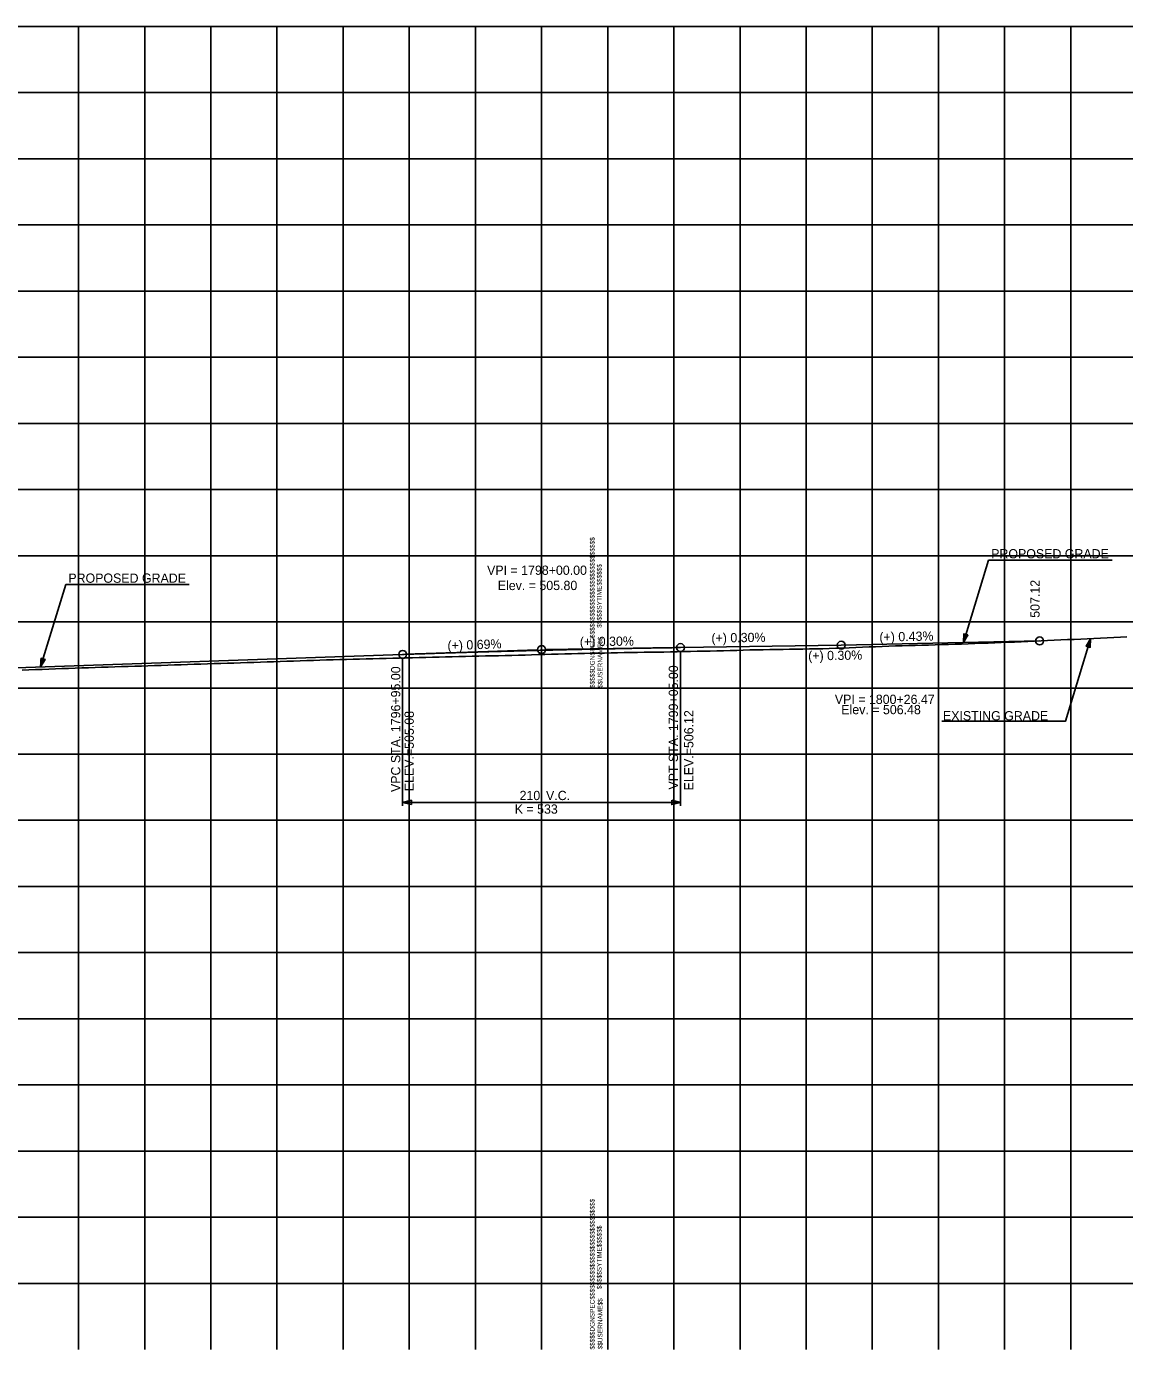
# Model space of a CAD drawing. Extents: x -90830 to 2015517, y -20856 to 836331.
# Drawn here: x 68334 to 69164, y -9797 to -8797 of the extents above; entities that cross this region are included whole.
import ezdxf

# ---------------------------------------------------------------- set-up
doc = ezdxf.new("R2010")
doc.units = 0
for name, color, linetype in [('Level 1', 7, 'Continuous'), ('RD_DDB_GradeTX', 7, 'Continuous'), ('RD_DDB_Profile_EX', 7, 'Continuous'), ('RD_DDB_Profile_Lbl', 7, 'Continuous'), ('RD_DDB_Profile_PR', 7, 'Continuous'), ('RD_DDB_StripGrade', 7, 'Continuous'), ('RD_DDB_VCLbl', 7, 'Continuous'), ('RD_PD_Final_TX', 7, 'Continuous')]:
    doc.layers.add(name, color=color, linetype=linetype)

msp = doc.modelspace()

# ---------------------------------------------------------------- linework, layer by layer
at = {"layer": 'Level 1'}
for p, q in [((67173.46, -8797.12), (68773.46, -8797.12)), ((68373.46, -8797.12), (68373.46, -9297.12)), ((68423.46, -8797.12), (68423.46, -9297.12)), ((68473.46, -8797.12), (68473.46, -9297.12)), ((68523.46, -8797.12), (68523.46, -9297.12)), ((68573.46, -8797.12), (68573.46, -9297.12)), ((68623.46, -8797.12), (68623.46, -9297.12)), ((68673.46, -8797.12), (68673.46, -9297.12)), ((68723.46, -8797.12), (68723.46, -9297.12)), ((68773.46, -8797.12), (68773.46, -9297.12)), ((68773.46, -8797.12), (68773.46, -9297.12)), ((68773.46, -8797.12), (70373.46, -8797.12)), ((68773.46, -8797.12), (68773.46, -9297.12)), ((68823.46, -8797.12), (68823.46, -9297.12)), ((68873.46, -8797.12), (68873.46, -9297.12)), ((68923.46, -8797.12), (68923.46, -9297.12)), ((68973.46, -8797.12), (68973.46, -9297.12)), ((69023.46, -8797.12), (69023.46, -9297.12)), ((69073.46, -8797.12), (69073.46, -9297.12)), ((69123.46, -8797.12), (69123.46, -9297.12)), ((67173.46, -8847.12), (68773.46, -8847.12)), ((68773.46, -8847.12), (70373.46, -8847.12)), ((67173.46, -8897.12), (68773.46, -8897.12)), ((68773.46, -8897.12), (70373.46, -8897.12)), ((67173.46, -8947.12), (68773.46, -8947.12)), ((68773.46, -8947.12), (70373.46, -8947.12)), ((67173.46, -8997.12), (68773.46, -8997.12)), ((68773.46, -8997.12), (70373.46, -8997.12)), ((67173.46, -9047.12), (68773.46, -9047.12)), ((68773.46, -9047.12), (70373.46, -9047.12)), ((67173.46, -9097.12), (68773.46, -9097.12)), ((68773.46, -9097.12), (70373.46, -9097.12)), ((67173.46, -9147.12), (68773.46, -9147.12)), ((68773.46, -9147.12), (70373.46, -9147.12)), ((67173.46, -9197.12), (68773.46, -9197.12)), ((68773.46, -9197.12), (70373.46, -9197.12)), ((67173.46, -9247.12), (68773.46, -9247.12)), ((68773.46, -9247.12), (70373.46, -9247.12)), ((67173.46, -9297.12), (68773.46, -9297.12)), ((67173.46, -9297.12), (68773.46, -9297.12)), ((68373.46, -9297.12), (68373.46, -9797.12)), ((68423.46, -9297.12), (68423.46, -9797.12)), ((68473.46, -9297.12), (68473.46, -9797.12)), ((68523.46, -9297.12), (68523.46, -9797.12)), ((68573.46, -9297.12), (68573.46, -9797.12)), ((68623.46, -9297.12), (68623.46, -9797.12)), ((68673.46, -9297.12), (68673.46, -9797.12)), ((68723.46, -9297.12), (68723.46, -9797.12)), ((68773.46, -9297.12), (68773.46, -9797.12)), ((68773.46, -9297.12), (68773.46, -9797.12)), ((68773.46, -9297.12), (70373.46, -9297.12)), ((68773.46, -9297.12), (70373.46, -9297.12)), ((68773.46, -9297.12), (68773.46, -9797.12)), ((68823.46, -9297.12), (68823.46, -9797.12)), ((68873.46, -9297.12), (68873.46, -9797.12)), ((68923.46, -9297.12), (68923.46, -9797.12)), ((68973.46, -9297.12), (68973.46, -9797.12)), ((69023.46, -9297.12), (69023.46, -9797.12)), ((69073.46, -9297.12), (69073.46, -9797.12)), ((69123.46, -9297.12), (69123.46, -9797.12)), ((67173.46, -9347.12), (68773.46, -9347.12)), ((68773.46, -9347.12), (70373.46, -9347.12)), ((67173.46, -9397.12), (68773.46, -9397.12)), ((68773.46, -9397.12), (70373.46, -9397.12)), ((67173.46, -9447.12), (68773.46, -9447.12)), ((68773.46, -9447.12), (70373.46, -9447.12)), ((67173.46, -9497.12), (68773.46, -9497.12)), ((68773.46, -9497.12), (70373.46, -9497.12)), ((67173.46, -9547.12), (68773.46, -9547.12)), ((68773.46, -9547.12), (70373.46, -9547.12)), ((67173.46, -9597.12), (68773.46, -9597.12)), ((68773.46, -9597.12), (70373.46, -9597.12)), ((67173.46, -9647.12), (68773.46, -9647.12)), ((68773.46, -9647.12), (70373.46, -9647.12)), ((67173.46, -9697.12), (68773.46, -9697.12)), ((68773.46, -9697.12), (70373.46, -9697.12)), ((67173.46, -9747.12), (68773.46, -9747.12)), ((68773.46, -9747.12), (70373.46, -9747.12))]:
    msp.add_line(p, q, dxfattribs=at)
at = {"layer": 'RD_DDB_GradeTX'}
for p, q in [((68652.5, -9270.56), (68720.46, -9268.21)), ((68794.45, -9267.05), (68726.46, -9268.06))]:
    msp.add_line(p, q, dxfattribs=at)
for centre in [(69099.93, -9261.54), (68723.46, -9268.1), (68949.93, -9264.73)]:
    msp.add_circle(centre, 3, dxfattribs=at)
at = {"layer": 'RD_DDB_Profile_EX'}
for points in [[(68920.95, -9267.68), (68925.95, -9267.6), (68930.95, -9267.51), (68935.95, -9267.43), (68940.95, -9267.28), (68945.95, -9267.09), (68950.95, -9266.9), (68955.95, -9266.72), (68960.95, -9266.52), (68965.95, -9266.3), (68970.95, -9266.09), (68975.95, -9265.88), (68980.95, -9265.69), (68985.95, -9265.52), (68990.95, -9265.36), (68995.95, -9265.19), (69000.95, -9265.04), (69005.95, -9264.9), (69010.95, -9264.77), (69015.95, -9264.64), (69020.95, -9264.5), (69025.95, -9264.35), (69030.95, -9264.2), (69035.95, -9264.05), (69040.95, -9263.88), (69045.95, -9263.69), (69050.95, -9263.49), (69055.95, -9263.3), (69060.95, -9263.11), (69065.95, -9262.92), (69070.95, -9262.74), (69075.95, -9262.55), (69080.95, -9262.36), (69085.95, -9262.14), (69090.95, -9261.92), (69095.95, -9261.71), (69100.95, -9261.5), (69105.95, -9261.26), (69110.95, -9261.03), (69115.95, -9260.8), (69120.95, -9260.58), (69125.95, -9260.36), (69130.95, -9260.15), (69135.95, -9259.94), (69140.95, -9259.73), (69145.95, -9259.5), (69150.95, -9259.27), (69155.95, -9259.04), (69160.95, -9258.81), (69165.95, -9258.57)], [(68420.95, -9280.51), (68425.95, -9280.35), (68430.95, -9280.18), (68435.95, -9280.02), (68440.95, -9279.85), (68445.95, -9279.69), (68450.95, -9279.54), (68455.95, -9279.39), (68460.95, -9279.22), (68465.95, -9279.04), (68470.95, -9278.86), (68475.95, -9278.69), (68480.95, -9278.53), (68485.95, -9278.38), (68490.95, -9278.23), (68495.95, -9278.08), (68500.95, -9277.91), (68505.95, -9277.74), (68510.95, -9277.57), (68515.95, -9277.39), (68520.95, -9277.23), (68525.95, -9277.07), (68530.95, -9276.92), (68535.95, -9276.76), (68540.95, -9276.59), (68545.95, -9276.42), (68550.95, -9276.25), (68555.95, -9276.08), (68560.95, -9275.94), (68565.95, -9275.81), (68570.95, -9275.68), (68575.95, -9275.54), (68580.95, -9275.41), (68585.95, -9275.29), (68590.95, -9275.16), (68595.95, -9275.05), (68600.95, -9274.92), (68605.95, -9274.8), (68610.95, -9274.68), (68615.95, -9274.56), (68620.95, -9274.44), (68625.95, -9274.32), (68630.95, -9274.19), (68635.95, -9274.06), (68640.95, -9273.92), (68645.95, -9273.79), (68650.95, -9273.65), (68655.95, -9273.51), (68660.95, -9273.38), (68665.95, -9273.26), (68670.95, -9273.14), (68675.95, -9273.01), (68680.95, -9272.9), (68685.95, -9272.8), (68690.95, -9272.7), (68695.95, -9272.6), (68700.95, -9272.47), (68705.95, -9272.33), (68710.95, -9272.19), (68715.95, -9272.05), (68720.95, -9271.91), (68725.95, -9271.78), (68730.95, -9271.64), (68735.95, -9271.51), (68740.95, -9271.38), (68745.95, -9271.26), (68750.95, -9271.14), (68755.95, -9271.02), (68760.95, -9270.91), (68765.95, -9270.79), (68770.95, -9270.67), (68775.95, -9270.56), (68780.95, -9270.46), (68785.95, -9270.38), (68790.95, -9270.29), (68795.95, -9270.21), (68800.95, -9270.13), (68805.95, -9270.06), (68810.95, -9269.99), (68815.95, -9269.92), (68820.95, -9269.82), (68825.95, -9269.72), (68830.95, -9269.61), (68835.95, -9269.5), (68840.95, -9269.4), (68845.95, -9269.29), (68850.95, -9269.19), (68855.95, -9269.08), (68860.95, -9268.94), (68865.95, -9268.8), (68870.95, -9268.65), (68875.95, -9268.5), (68880.95, -9268.39), (68885.95, -9268.29), (68890.95, -9268.2), (68895.95, -9268.11), (68900.95, -9268.02), (68905.95, -9267.93), (68910.95, -9267.85), (68915.95, -9267.77), (68920.95, -9267.68)], [(68330.95, -9283.56), (68335.95, -9283.4), (68340.95, -9283.22), (68345.95, -9283.04), (68350.95, -9282.86), (68355.95, -9282.68), (68360.95, -9282.5), (68365.95, -9282.32), (68370.95, -9282.14), (68375.95, -9281.97), (68380.95, -9281.79), (68385.95, -9281.62), (68390.95, -9281.44), (68395.95, -9281.27), (68400.95, -9281.11), (68405.95, -9280.96), (68410.95, -9280.81), (68415.95, -9280.67), (68420.95, -9280.51)]]:
    msp.add_lwpolyline(points, dxfattribs=at)
at = {"layer": 'RD_DDB_Profile_PR'}
for p, q in [((68828.46, -9266.54), (68949.93, -9264.73)), ((68949.93, -9264.73), (69099.93, -9261.54)), ((68028.46, -9292.15), (68618.46, -9271.74))]:
    msp.add_line(p, q, dxfattribs=at)
msp.add_spline([(68618.46, -9271.74), (68622.66, -9271.59), (68626.86, -9271.45), (68631.06, -9271.31), (68635.26, -9271.17), (68639.46, -9271.03), (68643.66, -9270.9), (68647.86, -9270.76), (68652.06, -9270.63), (68656.26, -9270.5), (68660.46, -9270.37), (68664.66, -9270.24), (68668.86, -9270.11), (68673.06, -9269.99), (68677.26, -9269.87), (68681.46, -9269.74), (68685.66, -9269.62), (68689.86, -9269.51), (68694.06, -9269.39), (68698.26, -9269.28), (68702.46, -9269.16), (68706.66, -9269.05), (68710.86, -9268.94), (68715.06, -9268.83), (68719.26, -9268.73), (68723.46, -9268.62), (68727.66, -9268.52), (68731.86, -9268.42), (68736.06, -9268.32), (68740.26, -9268.22), (68744.46, -9268.12), (68748.66, -9268.03), (68752.86, -9267.94), (68757.06, -9267.84), (68761.26, -9267.75), (68765.46, -9267.67), (68769.66, -9267.58), (68773.86, -9267.49), (68778.06, -9267.41), (68782.26, -9267.33), (68786.46, -9267.25), (68790.66, -9267.17), (68794.86, -9267.1), (68799.06, -9267.02), (68803.26, -9266.95), (68807.46, -9266.88), (68811.66, -9266.81), (68815.86, -9266.74), (68820.06, -9266.67), (68824.26, -9266.61), (68828.46, -9266.54)], degree=3, dxfattribs=at)
at = {"layer": 'RD_DDB_VCLbl'}
for p, q in [((68828.46, -9386.12), (68828.46, -9269.54)), ((68618.46, -9386.12), (68618.46, -9274.74)), ((68618.46, -9383.62), (68828.46, -9383.62))]:
    msp.add_line(p, q, dxfattribs=at)
for centre in [(68618.46, -9271.74), (68828.46, -9266.54)]:
    msp.add_circle(centre, 3, dxfattribs=at)
at = {"layer": 'RD_PD_Final_TX'}
for p, q in [((69042.28, -9262.77), (69061.34, -9200.4)), ((69061.34, -9200.4), (69154.72, -9200.4)), ((68344.76, -9281.21), (68363.81, -9218.84)), ((68363.81, -9218.84), (68457.2, -9218.84)), ((69042.28, -9262.77), (69042.63, -9256.1)), ((69044.17, -9256.57), (69042.28, -9262.77)), ((69042.28, -9262.77), (69045.72, -9257.04)), ((69042.63, -9256.1), (69045.72, -9257.04)), ((69138.45, -9259.84), (69135.01, -9265.56)), ((69136.56, -9266.03), (69138.45, -9259.84)), ((69138.45, -9259.84), (69138.11, -9266.51)), ((69138.11, -9266.51), (69135.01, -9265.56)), ((68344.76, -9281.21), (68345.1, -9274.54)), ((68346.65, -9275.01), (68344.76, -9281.21)), ((68344.76, -9281.21), (68348.2, -9275.48)), ((68345.1, -9274.54), (68348.2, -9275.48))]:
    msp.add_line(p, q, dxfattribs=at)
for points in [[(69026.01, -9322.21), (69119.4, -9322.21), (69138.45, -9259.84)], [(69044.11, -9256.63), (69042.34, -9262.4), (69044.08, -9256.58), (69042.37, -9262.12), (69044.01, -9256.59), (69042.38, -9261.92), (69043.93, -9256.58), (69042.38, -9261.69), (69043.87, -9256.55), (69042.41, -9261.33), (69043.78, -9256.51), (69042.44, -9260.95), (69043.7, -9256.51), (69042.46, -9260.66), (69043.64, -9256.48), (69042.47, -9260.33), (69043.56, -9256.49), (69042.49, -9260.04), (69043.51, -9256.42), (69042.5, -9259.79), (69043.41, -9256.42), (69042.51, -9259.43), (69043.34, -9256.39), (69042.56, -9258.99), (69043.27, -9256.35), (69042.54, -9258.69), (69043.19, -9256.33), (69042.56, -9258.24), (69043.11, -9256.33), (69042.61, -9257.87), (69043.03, -9256.26), (69042.62, -9257.55), (69042.96, -9256.27), (69042.62, -9257.26), (69042.89, -9256.21), (69042.65, -9256.9), (69042.81, -9256.24), (69042.67, -9256.5), (69042.73, -9256.24)], [(69042.45, -9262.38), (69044.2, -9256.66), (69042.55, -9262.19), (69044.27, -9256.68), (69042.65, -9262), (69044.33, -9256.67), (69042.77, -9261.84), (69044.38, -9256.7), (69042.9, -9261.65), (69044.45, -9256.71), (69043.01, -9261.46), (69044.5, -9256.72), (69043.15, -9261.23), (69044.57, -9256.73), (69043.3, -9260.96), (69044.65, -9256.77), (69043.43, -9260.72), (69044.71, -9256.76), (69043.58, -9260.47), (69044.77, -9256.79), (69043.73, -9260.23), (69044.84, -9256.81), (69043.89, -9259.97), (69044.88, -9256.87), (69044.09, -9259.63), (69044.95, -9256.86), (69044.24, -9259.41), (69045.01, -9256.85), (69044.43, -9259.11), (69045.06, -9256.9), (69044.58, -9258.81), (69045.14, -9256.93), (69044.72, -9258.57), (69045.2, -9257), (69044.88, -9258.36), (69045.25, -9257.01), (69045.06, -9258), (69045.36, -9256.99), (69045.18, -9257.8), (69045.46, -9257.02), (69045.3, -9257.67), (69045.54, -9257.11), (69045.63, -9257.07), (69045.52, -9257.11)], [(69138.28, -9260.22), (69136.54, -9265.94), (69138.18, -9260.42), (69136.46, -9265.92), (69138.08, -9260.6), (69136.4, -9265.93), (69137.96, -9260.76), (69136.35, -9265.9), (69137.83, -9260.96), (69136.28, -9265.89), (69137.72, -9261.15), (69136.23, -9265.88), (69137.58, -9261.37), (69136.16, -9265.87), (69137.43, -9261.65), (69136.08, -9265.83), (69137.3, -9261.89), (69136.02, -9265.84), (69137.15, -9262.14), (69135.96, -9265.81), (69137, -9262.37), (69135.9, -9265.79), (69136.85, -9262.63), (69135.86, -9265.73), (69136.64, -9262.98), (69135.78, -9265.74), (69136.49, -9263.2), (69135.72, -9265.75), (69136.3, -9263.49), (69135.67, -9265.71), (69136.15, -9263.79), (69135.6, -9265.67), (69136.01, -9264.03), (69135.53, -9265.61), (69135.85, -9264.25), (69135.48, -9265.59), (69135.67, -9264.6), (69135.37, -9265.62), (69135.55, -9264.8), (69135.27, -9265.58), (69135.43, -9264.93), (69135.19, -9265.49), (69135.1, -9265.53), (69135.21, -9265.5)], [(69136.62, -9265.97), (69138.39, -9260.2), (69136.65, -9266.02), (69138.36, -9260.49), (69136.72, -9266.01), (69138.35, -9260.68), (69136.8, -9266.02), (69138.35, -9260.92), (69136.86, -9266.06), (69138.33, -9261.27), (69136.95, -9266.1), (69138.29, -9261.66), (69137.04, -9266.1), (69138.27, -9261.95), (69137.1, -9266.13), (69138.26, -9262.28), (69137.17, -9266.11), (69138.24, -9262.57), (69137.22, -9266.18), (69138.23, -9262.82), (69137.32, -9266.18), (69138.22, -9263.18), (69137.39, -9266.22), (69138.17, -9263.61), (69137.46, -9266.25), (69138.19, -9263.91), (69137.54, -9266.28), (69138.17, -9264.37), (69137.62, -9266.28), (69138.12, -9264.73), (69137.7, -9266.34), (69138.11, -9265.05), (69137.77, -9266.34), (69138.11, -9265.34), (69137.84, -9266.4), (69138.08, -9265.7), (69137.92, -9266.37), (69138.06, -9266.1), (69138, -9266.36)], [(68346.58, -9275.07), (68344.82, -9280.84), (68346.55, -9275.02), (68344.85, -9280.56), (68346.48, -9275.03), (68344.85, -9280.36), (68346.4, -9275.02), (68344.85, -9280.12), (68346.34, -9274.99), (68344.88, -9279.77), (68346.25, -9274.94), (68344.91, -9279.39), (68346.17, -9274.95), (68344.93, -9279.1), (68346.11, -9274.91), (68344.95, -9278.77), (68346.03, -9274.93), (68344.97, -9278.48), (68345.99, -9274.86), (68344.97, -9278.23), (68345.89, -9274.86), (68344.98, -9277.87), (68345.81, -9274.82), (68345.03, -9277.43), (68345.74, -9274.79), (68345.01, -9277.13), (68345.66, -9274.76), (68345.04, -9276.68), (68345.58, -9274.77), (68345.08, -9276.31), (68345.5, -9274.7), (68345.09, -9275.99), (68345.43, -9274.71), (68345.1, -9275.7), (68345.36, -9274.65), (68345.12, -9275.34), (68345.28, -9274.68), (68345.15, -9274.94), (68345.2, -9274.68)], [(68344.92, -9280.82), (68346.67, -9275.1), (68345.02, -9280.62), (68346.75, -9275.12), (68345.12, -9280.44), (68346.81, -9275.11), (68345.24, -9280.28), (68346.85, -9275.14), (68345.37, -9280.09), (68346.92, -9275.15), (68345.48, -9279.9), (68346.97, -9275.16), (68345.62, -9279.67), (68347.04, -9275.17), (68345.78, -9279.4), (68347.13, -9275.21), (68345.91, -9279.16), (68347.19, -9275.2), (68346.05, -9278.91), (68347.25, -9275.23), (68346.21, -9278.67), (68347.31, -9275.25), (68346.36, -9278.41), (68347.35, -9275.31), (68346.56, -9278.07), (68347.42, -9275.3), (68346.71, -9277.85), (68347.48, -9275.29), (68346.9, -9277.55), (68347.54, -9275.34), (68347.05, -9277.25), (68347.61, -9275.37), (68347.19, -9277.01), (68347.67, -9275.43), (68347.36, -9276.8), (68347.73, -9275.45), (68347.53, -9276.44), (68347.83, -9275.43), (68347.65, -9276.24), (68347.93, -9275.46), (68347.78, -9276.11), (68348.02, -9275.55), (68348.1, -9275.51), (68347.99, -9275.55)]]:
    msp.add_lwpolyline(points, dxfattribs=at)
for points in [[(68625.06, -9385.27), (68618.46, -9383.62), (68625.06, -9381.97)], [(68821.86, -9381.97), (68828.46, -9383.62), (68821.86, -9385.27)]]:
    msp.add_lwpolyline(points, close=True, dxfattribs=at)

# ---------------------------------------------------------------- texts
at = {"layer": 'Level 1'}
for s, p in [('$$$$$DGNSPEC$$$$$$$$$$$$$$$$$$$$$$$$$$$$', (68763.56, -9297.17)), ('$$$$$SYTIME$$$$$$', (68768.86, -9251.57)), ('$$USERNAME$$', (68769.46, -9297.02)), ('$$$$$DGNSPEC$$$$$$$$$$$$$$$$$$$$$$$$$$$$', (68763.56, -9797.17)), ('$$$$$SYTIME$$$$$$', (68768.86, -9751.57)), ('$$USERNAME$$', (68769.46, -9797.02))]:
    msp.add_text(s, height=3.5436, rotation=90, dxfattribs=at).set_placement(p)
at = {"layer": 'RD_DDB_GradeTX'}
for s, rotation, p in [('(+) 0.30%', 0.85247, (68752.42, -9265.67)), ('(+) 0.30%', 0.85247, (68851.89, -9262.84)), ('(+) 0.43%', 1.22058, (68978.88, -9262.12)), ('(+) 0.69%', 1.98146, (68652.43, -9268.56)), ('(+) 0.30%', 0.85247, (68925.02, -9276.28))]:
    msp.add_text(s, height=7, rotation=rotation, dxfattribs=at).set_placement(p)
at = {"layer": 'RD_DDB_Profile_Lbl'}
for s, p in [('VPI = 1798+00.00', (68682.27, -9211.6)), ('Elev. = 505.80', (68690.34, -9223.1)), ('VPI = 1800+26.47', (68945.12, -9309.17)), ('Elev. = 506.48', (68950.01, -9316.93))]:
    msp.add_text(s, height=7, dxfattribs=at).set_placement(p)
msp.add_text('507.12', height=7, rotation=90, dxfattribs=at).set_placement((69099.93, -9244.04))
at = {"layer": 'RD_DDB_StripGrade'}
for s, p in [('VPC STA. 1796+95.00 ', (68616.69, -9375.74)), ('VPT STA. 1799+05.00 ', (68826.56, -9373.89)), ('ELEV.=505.08', (68626.89, -9375.12)), ('ELEV.=506.12', (68838.23, -9374.51))]:
    msp.add_text(s, height=7, rotation=90, dxfattribs=at).set_placement(p)
at = {"layer": 'RD_DDB_VCLbl'}
for s, p in [("210' V.C.", (68706.82, -9381.85)), ('K = 533', (68703.17, -9392.13))]:
    msp.add_text(s, height=7, dxfattribs=at).set_placement(p)
at = {"layer": 'RD_PD_Final_TX'}
for s, p in [('PROPOSED GRADE', (69063.29, -9199.14)), ('PROPOSED GRADE', (68365.76, -9217.58)), ('EXISTING GRADE', (69026.83, -9321.6))]:
    msp.add_text(s, height=7, dxfattribs=at).set_placement(p)

doc.saveas('drawing.dxf')
